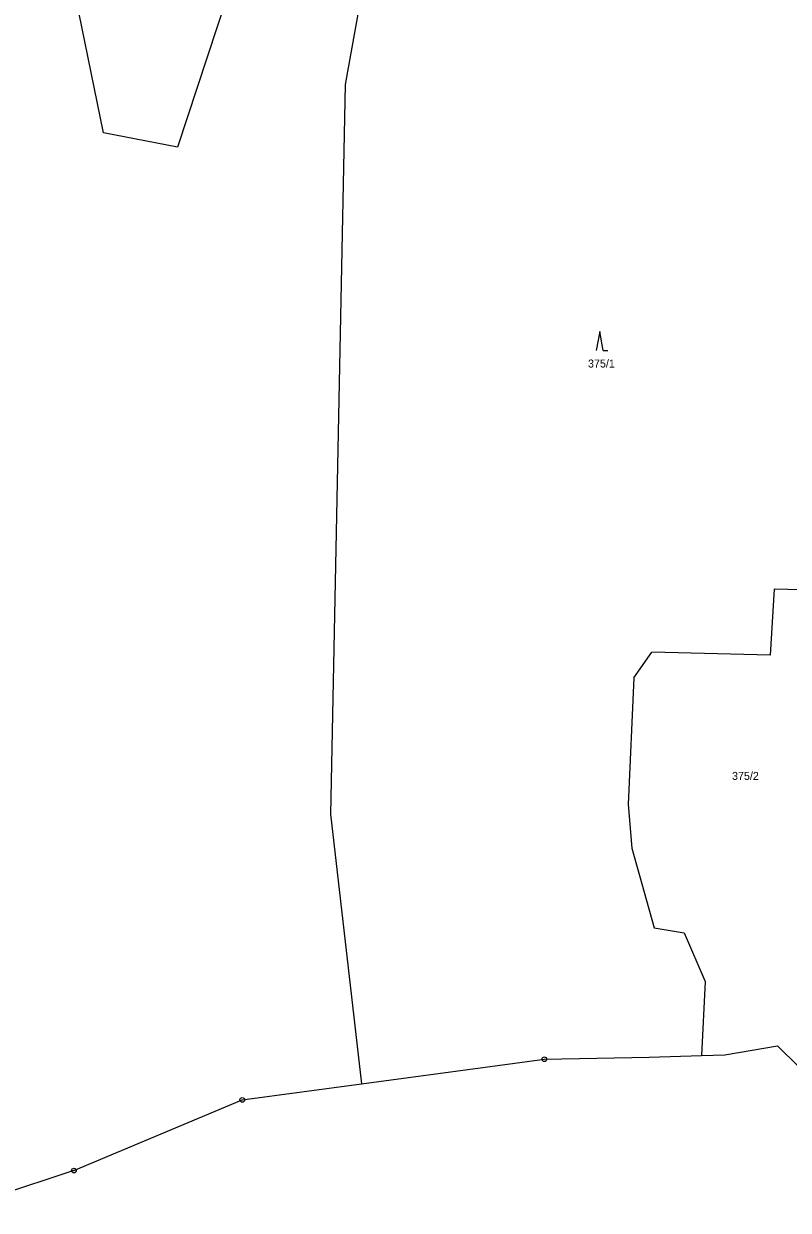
# Model space of a CAD drawing. Extents: x -765428 to -762163, y -1107632 to -1104975.
# Drawn here: x -764502 to -764339.7, y -1107132.3 to -1106880.1 of the extents above; entities that cross this region are included whole.
import ezdxf
from ezdxf.enums import TextEntityAlignment as Align

# ---------------------------------------------------------------- set-up
doc = ezdxf.new("R2010")
doc.units = 0
doc.header["$LTSCALE"] = 0.68
for name, color, linetype, lineweight in [('1', 7, 'Continuous', 25), ('3', 7, 'Continuous', 25), ('8', 7, 'Continuous', 25)]:
    doc.layers.add(name, color=color, linetype=linetype, lineweight=lineweight)
doc.layers.add('2', color=7, linetype='Continuous')

msp = doc.modelspace()

# ---------------------------------------------------------------- linework, layer by layer
at = {"layer": '1'}
for p, q in [((-764420.5, -1106819.24), (-764433.75, -1106893.03)), ((-764450.3, -1106848.47), (-764469.37, -1106906.36)), ((-764485.09, -1106903.35), (-764495.43, -1106852.84)), ((-764433.75, -1106893.03), (-764436.88, -1107048.07)), ((-764469.37, -1106906.36), (-764485.09, -1106903.35)), ((-764342.65, -1107000.26), (-764343.5, -1107014.29)), ((-764325.8, -1107000.77), (-764342.65, -1107000.26)), ((-764372.46, -1107019.15), (-764368.67, -1107013.69)), ((-764343.5, -1107014.29), (-764368.67, -1107013.69)), ((-764372.46, -1107019.15), (-764373.65, -1107046.06)), ((-764436.88, -1107048.07), (-764430.33, -1107105.41)), ((-764373.65, -1107046.06), (-764372.89, -1107055.32)), ((-764372.89, -1107055.32), (-764368.16, -1107072.27)), ((-764368.16, -1107072.27), (-764361.77, -1107073.29)), ((-764361.77, -1107073.29), (-764357.29, -1107083.67)), ((-764357.29, -1107083.67), (-764358.07, -1107099.39)), ((-764353.11, -1107099.22), (-764341.92, -1107097.33)), ((-764341.92, -1107097.33), (-764337.42, -1107101.76)), ((-764430.33, -1107105.41), (-764391.46, -1107100.17)), ((-764391.46, -1107100.17), (-764369.22, -1107099.76)), ((-764369.22, -1107099.76), (-764358.07, -1107099.39)), ((-764358.07, -1107099.39), (-764353.11, -1107099.22)), ((-764455.63, -1107108.82), (-764430.33, -1107105.41)), ((-764491.38, -1107123.83), (-764455.63, -1107108.82)), ((-764491.38, -1107123.83), (-764517.09, -1107132.27))]:
    msp.add_line(p, q, dxfattribs=at)
at = {"layer": '3'}
msp.add_line((-764378.95, -1106949.55), (-764377.954, -1106949.55), dxfattribs=at)
msp.add_lwpolyline([(-764378.95, -1106949.55), (-764379.7, -1106945.55), (-764380.45, -1106949.55)], dxfattribs=at)
at = {"layer": '8'}
for centre, radius in [((-764391.46, -1107100.1699), 0.5), ((-764391.46, -1107100.1699), 0.0303), ((-764455.63, -1107108.8199), 0.5), ((-764455.63, -1107108.8199), 0.0303), ((-764491.38, -1107123.8299), 0.5), ((-764491.38, -1107123.8299), 0.0303)]:
    msp.add_circle(centre, radius, dxfattribs=at)

# ---------------------------------------------------------------- texts
at = {"layer": '2'}
msp.add_text('375/1', height=1.7, dxfattribs=at).set_placement((-764379.35, -1106953.195), align=Align.CENTER)
msp.add_text('375/2', height=1.7, dxfattribs=at).set_placement((-764351.61, -1107040.825))

doc.saveas('drawing.dxf')
